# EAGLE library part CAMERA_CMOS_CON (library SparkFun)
640x480 CMOS Color Camera Footprint proven. Spark Fun Electronics Camera SKU : Sense-CCam, Mating Connector SKU : Sense-CCam-Connector
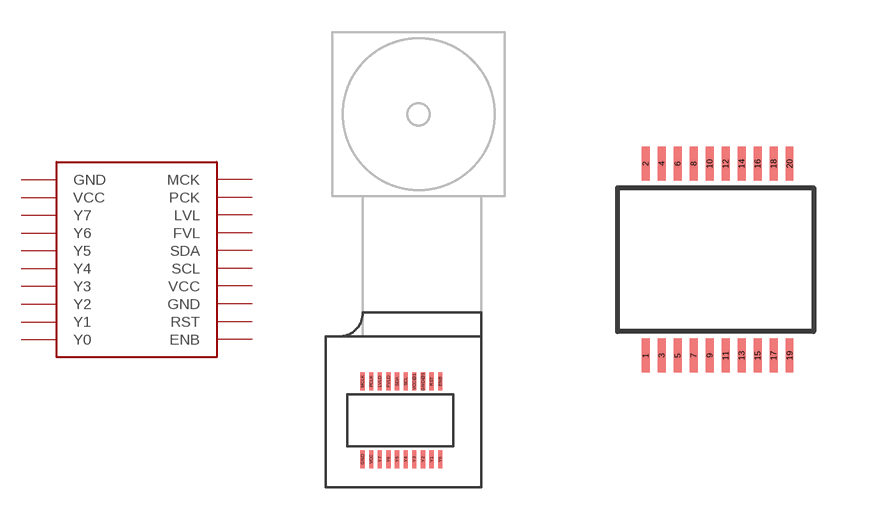
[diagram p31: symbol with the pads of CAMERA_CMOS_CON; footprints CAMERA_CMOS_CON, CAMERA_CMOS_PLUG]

Designator prefix -

## CAMERA_CMOS_CONSMD  [CAMERA_CMOS_CON]
ENB  ENB
FVLD  FVL
GND  GND
GND@1  GND
LVLD  LVL
MCLK  MCK
PCLK  PCK
RST  RST
SCL  SCL
SDA  SDA
VCC  VCC
VCC@1  VCC
Y0  Y0
Y1  Y1
Y2  Y2
Y3  Y3
Y4  Y4
Y5  Y5
Y6  Y6
Y7  Y7

## CAMERA_CMOS_CONPLUG  [CAMERA_CMOS_PLUG]
1  Y0
2  Y1
3  Y2
4  Y3
5  Y4
6  Y5
7  Y6
8  Y7
9  VCC
10  GND
11  ENB
12  RST
13  GND
14  VCC
15  SCL
16  SDA
17  FVL
18  LVL
19  PCK
20  MCK

## Footprint CAMERA_CMOS_CON (pad centres in mm)
smd 0.2 x 0.83: ENB 3.6,1.8; FVLD 1.2,1.8; GND 0,-1.8; GND@1 2.8,1.8; LVLD 0.8,1.8; MCLK 0,1.8; PCLK 0.4,1.8; RST 3.2,1.8; SCL 2,1.8; SDA 1.6,1.8; VCC 0.4,-1.8; VCC@1 2.4,1.8; Y0 3.6,-1.8; Y1 3.2,-1.8; Y2 2.8,-1.8; Y3 2.4,-1.8; Y4 2,-1.8; Y5 1.6,-1.8; Y6 1.2,-1.8; Y7 0.8,-1.8

## Footprint CAMERA_CMOS_PLUG (pad centres in mm)
smd 0.2 x 0.85: 1 0.7,-2.4; 2 0.7,2.4; 3 1.1,-2.4; 4 1.1,2.4; 5 1.5,-2.4; 6 1.5,2.4; 7 1.9,-2.4; 8 1.9,2.4; 9 2.3,-2.4; 10 2.3,2.4; 11 2.7,-2.4; 12 2.7,2.4; 13 3.1,-2.4; 14 3.1,2.4; 15 3.5,-2.4; 16 3.5,2.4; 17 3.9,-2.4; 18 3.9,2.4; 19 4.3,-2.4; 20 4.3,2.4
